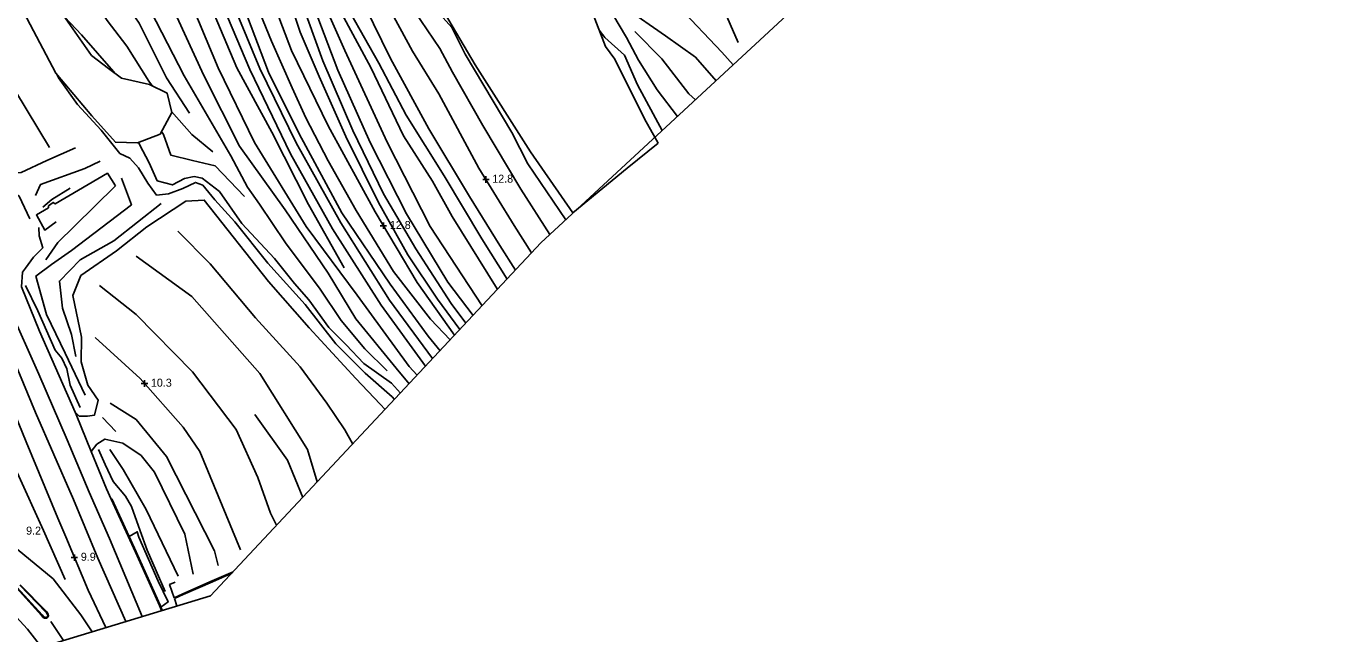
# Model space of a CAD drawing. Extents: x 2316231 to 2323598, y 363169 to 371906.
# Drawn here: x 2321107 to 2321928, y 365823 to 366202 of the extents above; entities that cross this region are included whole.
import ezdxf

# ---------------------------------------------------------------- set-up
doc = ezdxf.new("R2010")
doc.units = 0
for name, color, linetype in [('RD_DTM_BkLn1', 7, 'Continuous'), ('RD_DTM_Holes', 7, 'Continuous'), ('RD_DTM_TinHull', 7, 'Continuous'), ('RD_DTM_Void', 7, 'Continuous'), ('RD_EX_Road', 7, 'Continuous')]:
    doc.layers.add(name, color=color, linetype=linetype)

msp = doc.modelspace()

# ---------------------------------------------------------------- linework, layer by layer
at = {"layer": 'RD_DTM_BkLn1'}
for p, q in [((2321322.227, 366176.768), (2321286.129, 366244.099)), ((2321289.965, 366171.094), (2321277.994, 366198.719)), ((2321504.083, 366182.051), (2321487.214, 366199.217)), ((2321273.167, 366164.035), (2321260.269, 366193.113)), ((2321525.098, 366183.196), (2321537.836, 366168.43)), ((2321541.433, 366186.303), (2321548.52, 366178.333)), ((2321161.522, 366174.213), (2321162.22, 366173.211)), ((2321194.551, 366170.281), (2321208.955, 366148.228)), ((2321183.535, 366168.208), (2321185.773, 366165.108)), ((2321135.268, 366009.871), (2321137.957, 365996.082)), ((2321154.562, 365958.083), (2321162.89, 365949.247)), ((2321158.973, 365882.361), (2321179.414, 365833.696)), ((2321107.857, 365825.845), (2321116.44, 365814.555)), ((2321122.287, 365830.606), (2321130.227, 365818.746))]:
    msp.add_line(p, q, dxfattribs=at)
for points in [[(2321348.15, 366186.893), (2321331.232, 366218.438), (2321308.543, 366258.039), (2321292.715, 366289.297), (2321276.233, 366327.234), (2321257.319, 366369.632), (2321242.916, 366404.393), (2321227.689, 366445.074), (2321218.8, 366481.104), (2321211.429, 366515.501), (2321205.646, 366550.168), (2321200.699, 366594.349), (2321199.591, 366605.689)], [(2321301.702, 366175.097), (2321280.565, 366230.673), (2321263.475, 366276.886), (2321246.42, 366324.965), (2321229.201, 366379.671), (2321213.13, 366435.047), (2321200.953, 366481.482), (2321193.69, 366533.508), (2321189.529, 366581.697), (2321189.106, 366587.086)], [(2321292.167, 366180.958), (2321272.992, 366233.91), (2321255.426, 366283.859), (2321234.365, 366343.224), (2321216.164, 366402.709), (2321203.601, 366449.019), (2321195.314, 366487.774), (2321188.211, 366534.023), (2321184.436, 366578.801)], [(2321277.994, 366198.719), (2321258.305, 366258.009), (2321242.246, 366306.595), (2321223.445, 366361.989), (2321203.844, 366426.687), (2321190.102, 366483.073), (2321182.297, 366539.349), (2321179.687, 366570.375)], [(2321272.7, 366187.357), (2321259.187, 366223.155), (2321241.08, 366276.024), (2321219.601, 366347.455), (2321202.66, 366410.513), (2321186.289, 366461.213), (2321172.327, 366507.777), (2321166.852, 366547.603)], [(2321260.269, 366193.113), (2321240.792, 366240.711), (2321224.219, 366294.328), (2321207.131, 366346.117), (2321191.769, 366401.079), (2321171.604, 366468.511), (2321156.376, 366512.529), (2321153.71, 366524.287)], [(2321252.801, 366176.011), (2321231.979, 366226.491), (2321212.413, 366277.422), (2321195.559, 366329.186), (2321179.21, 366383.175), (2321162.803, 366442.321), (2321144.808, 366504.734), (2321144.106, 366507.248)], [(2321258.386, 366173.779), (2321242.805, 366214.365), (2321221.841, 366267.452), (2321204.934, 366313.185), (2321195.458, 366348.589), (2321191.131, 366367.553), (2321174.763, 366418.778), (2321160.755, 366467.057), (2321147.297, 366512.909)], [(2321327.165, 366179.472), (2321300.339, 366227.015), (2321278.298, 366267.649), (2321261.143, 366307.819), (2321239.141, 366360.878), (2321224.082, 366400.555), (2321212.067, 366448.483), (2321203.9, 366496.151)], [(2321238.425, 366176.556), (2321222.092, 366215.463), (2321205.055, 366259.307), (2321191.459, 366296.15), (2321183.264, 366326.085), (2321173.84, 366353.695), (2321159.577, 366397.181), (2321142.653, 366442.133), (2321123.393, 366483.161)], [(2321246.543, 366175.521), (2321216.416, 366246.921), (2321192.369, 366316.631), (2321175.26, 366368.689), (2321160.219, 366410.815), (2321138.931, 366462.563), (2321127.39, 366487.452)], [(2321226.83, 366176.404), (2321207.135, 366223.931), (2321188.206, 366277.599), (2321173.929, 366325.811), (2321158.597, 366363.074), (2321147.977, 366412.054), (2321131.316, 366452.804), (2321118.411, 366477.812)], [(2321217.85, 366171.777), (2321195.092, 366221.773), (2321177.651, 366264.476), (2321159.843, 366311.615), (2321145.632, 366336.983), (2321130.053, 366374.015), (2321112.686, 366422.481), (2321099.314, 366457.31)], [(2321205.698, 366171.431), (2321181.155, 366219.069), (2321161.671, 366246.316), (2321145.676, 366287.224), (2321131.683, 366315.53), (2321109.87, 366367.188), (2321090.922, 366404.593), (2321078.335, 366434.787)], [(2321511.284, 366313.643), (2321496.519, 366319.473), (2321484.027, 366320.013), (2321478.066, 366308.212), (2321479.658, 366290.223), (2321482.685, 366260.265), (2321481.649, 366243.589), (2321476.829, 366234.895), (2321468.495, 366229.189), (2321481.143, 366213.982), (2321506.351, 366196.403), (2321525.098, 366183.196)], [(2321306.074, 366187.392), (2321285.761, 366232.924), (2321262.685, 366291.02)], [(2321541.433, 366186.303), (2321514.561, 366214.605), (2321500.215, 366233.93), (2321495.065, 366255.432), (2321501.651, 366264.779), (2321512.378, 366258.732), (2321535.225, 366230.284), (2321551.695, 366192.277)], [(2321381.088, 366185.114), (2321372.744, 366201.657), (2321365.438, 366209.827), (2321362.911, 366215.561), (2321353.959, 366228.701), (2321353.362, 366236.235)], [(2321194.551, 366170.281), (2321177.542, 366204.311), (2321161.58, 366227.941)], [(2321455.195, 366229.198), (2321459.015, 366226.442), (2321462.737, 366221.353), (2321473.333, 366209.87), (2321481.88, 366195.503)], [(2321183.535, 366168.208), (2321169.755, 366189.956), (2321157.441, 366206.094), (2321146.286, 366222.901)], [(2321161.522, 366174.213), (2321141.489, 366197.161), (2321130.996, 366208.151)], [(2321121.498, 366126.801), (2321100.307, 366161.879), (2321090.1, 366195.438)], [(2321480.738, 366184.491), (2321468.334, 366195.356), (2321464.878, 366200.017)], [(2321481.88, 366195.503), (2321489.421, 366181.323), (2321500.985, 366162.838), (2321513.758, 366146.112)], [(2321272.7, 366187.357), (2321295.585, 366140.192), (2321324.959, 366086.53), (2321351.072, 366042.351), (2321374.541, 366009.457)], [(2321306.074, 366187.392), (2321332.414, 366130.151), (2321359.258, 366077.265), (2321391.724, 366027.81)], [(2321348.15, 366186.893), (2321364.743, 366160.239), (2321389.693, 366113.829), (2321411.738, 366078.055), (2321422.627, 366060.816)], [(2321292.167, 366180.958), (2321310.912, 366137.272), (2321330.156, 366097.692), (2321350.269, 366063.337), (2321372.395, 366029.323), (2321381.548, 366016.941)], [(2321327.165, 366179.472), (2321344.311, 366147.021), (2321368.067, 366109.11), (2321391.568, 366069.738), (2321407.336, 366044.484)], [(2321381.088, 366185.114), (2321410.249, 366136.134), (2321420.299, 366116.534), (2321444.024, 366081.475)], [(2321480.738, 366184.491), (2321488.743, 366165.791), (2321504.223, 366137.274)], [(2321504.083, 366182.051), (2321520.948, 366160.227), (2321525.075, 366156.602)], [(2321033.694, 366176.556), (2321049.251, 366136.951), (2321066.065, 366097.733), (2321080.078, 366064.138), (2321096.325, 366026.829), (2321114.881, 365985.178), (2321132.594, 365944.069), (2321146.359, 365911.495), (2321158.973, 365882.361)], [(2321217.367, 366103.276), (2321212.625, 366104.93), (2321204.731, 366101.187), (2321195.743, 366097.753), (2321188.43, 366096.97), (2321182.981, 366104.494), (2321177.014, 366114.093), (2321171.615, 366119.963), (2321165.471, 366122.934), (2321153.871, 366137.579), (2321139.085, 366153.645), (2321127.048, 366170.221), (2321126.144, 366172.319)], [(2321205.698, 366171.431), (2321221.677, 366143.993), (2321234.717, 366121.531), (2321245.215, 366101.866), (2321252.706, 366091.256), (2321268.811, 366067.267), (2321290.645, 366038.255), (2321303.614, 366018.737), (2321318.543, 366000.908), (2321332.317, 365987.135)], [(2321217.85, 366171.777), (2321240.157, 366127.55), (2321268.747, 366087.795), (2321295.543, 366048.263), (2321312.928, 366019.78), (2321338.116, 365988.765), (2321346.192, 365979.179)], [(2321226.83, 366176.404), (2321249.451, 366129.904), (2321281.758, 366077.317), (2321313.737, 366034.483), (2321346.059, 365989.836), (2321351.126, 365984.448)], [(2321238.425, 366176.556), (2321260.333, 366136.375), (2321283.311, 366091.077), (2321305.57, 366051.601)], [(2321246.543, 366175.521), (2321272.005, 366122.782), (2321298.214, 366075.883), (2321328.678, 366028.152), (2321356.365, 365990.044)], [(2321252.801, 366176.011), (2321275.554, 366129.71), (2321303.496, 366079.623), (2321333.953, 366031.325), (2321360.832, 365994.815)], [(2321258.386, 366173.779), (2321277.513, 366135.24), (2321304.118, 366085.985), (2321334.325, 366041.27), (2321358.076, 366008.761), (2321365.494, 365999.794)], [(2321289.965, 366171.094), (2321306.541, 366133.592), (2321327.089, 366092.436), (2321345.414, 366059.734), (2321363.86, 366032.005), (2321377.815, 366012.954)], [(2321301.702, 366175.097), (2321321.834, 366129.857), (2321344.395, 366085.19), (2321370.302, 366042.62), (2321386.041, 366021.739)], [(2321322.227, 366176.768), (2321342.555, 366134.043), (2321360.673, 366105.633), (2321372.938, 366083.571), (2321401.166, 366038.479), (2321401.4, 366038.144)], [(2321016.422, 366163.653), (2321030.631, 366126.842), (2321048.807, 366082.123), (2321067.3, 366038.239), (2321086.527, 365992.491), (2321107.017, 365942.839), (2321126.727, 365895.111), (2321131.653, 365883.468)], [(2321028.335, 366166.59), (2321046.266, 366121.165), (2321067.619, 366067.708), (2321091.625, 366011.903), (2321112.764, 365961.191), (2321135.654, 365908.779)], [(2321273.167, 366164.035), (2321281.561, 366145.247), (2321295.491, 366118.343), (2321313.082, 366087.422), (2321336.386, 366049.281), (2321359.556, 366019.425), (2321371.747, 366006.473)], [(2321107.857, 365825.845), (2321089.033, 365845.956), (2321064.914, 365868.827), (2321040.152, 365890.43), (2321013.859, 365911.449), (2320983.706, 365933.792), (2320958.395, 365951.148), (2320936.89, 365964.698), (2320914.976, 365977.721), (2320890.131, 365990.721), (2320868.682, 366001.198), (2320834.466, 366016.123), (2320800.88, 366029.386), (2320770.06, 366041.822), (2320731.461, 366056.849), (2320690.819, 366072.905), (2320650.247, 366088.926), (2320609.558, 366105.101), (2320574.835, 366119.134), (2320536.92, 366134.034), (2320494.89, 366150.627)], [(2321197.687, 366149.254), (2321210.444, 366134.867), (2321223.532, 366123.927)], [(2321216.793, 366107.549), (2321211.842, 366108.544), (2321205.741, 366107.355), (2321198.246, 366103.324), (2321188.754, 366105.994), (2321183.859, 366117.164), (2321177.738, 366128.632), (2321177.187, 366130.003)], [(2321191.455, 366136.714), (2321192.705, 366134.887), (2321197.237, 366121.973), (2321210.773, 366118.602), (2321225.078, 366115.175), (2321243.407, 366096.134)], [(2321153.217, 366118.241), (2321143.492, 366113.552), (2321115.787, 366103.697), (2321112.795, 366096.809)], [(2321109.125, 366082.059), (2321102.556, 366096.416), (2321095.113, 366101.366), (2321086.105, 366105.886)], [(2321143.851, 365972.008), (2321131.365, 365998.173), (2321119.67, 366022.32), (2321112.985, 366046.416), (2321122.648, 366053.73), (2321135.305, 366062.365), (2321172.673, 366090.996), (2321166.557, 366107.617)], [(2321216.793, 366107.549), (2321227.787, 366099.211), (2321241.601, 366079.174), (2321262.106, 366057.388), (2321274.534, 366041.788), (2321283.411, 366031.491), (2321295.924, 366014.188), (2321306.863, 366003.393), (2321317.805, 365991.841), (2321335.024, 365979.526), (2321340.644, 365973.252)], [(2321162.784, 366102.736), (2321137.149, 366077.634), (2321126.729, 366067.364), (2321119.149, 366056.515)], [(2321217.367, 366103.276), (2321224.803, 366094.036), (2321237.219, 366080.28), (2321257.933, 366054.426), (2321281.295, 366028.61), (2321300.288, 366004.006), (2321318.662, 365985.709), (2321335.543, 365970.928), (2321337.012, 365969.373)], [(2321191.318, 366091.663), (2321161.733, 366068.324), (2321140.705, 366056.59), (2321127.658, 366043.244), (2321129.564, 366026.392), (2321135.268, 366009.871)], [(2321201.729, 366074.457), (2321221.897, 366054.07), (2321250.148, 366020.393), (2321278.059, 365989.676), (2321294.748, 365967.027), (2321305.885, 365950.285), (2321310.88, 365941.463)], [(2321175.606, 366058.769), (2321210.392, 366033.591), (2321252.8, 365985.522), (2321282.723, 365937.975), (2321288.702, 365917.776)], [(2321152.667, 366040.571), (2321175.687, 366022.428), (2321210.719, 365986.611), (2321238.172, 365950.487), (2321251.532, 365920.458), (2321259.494, 365898.355), (2321263.365, 365890.714)], [(2321150.064, 366007.939), (2321178.109, 365982.395), (2321204.889, 365952.023)], [(2321159.377, 365967.076), (2321175.557, 365956.712), (2321194.592, 365933.585), (2321224.658, 365874.726), (2321226.777, 365865.494)], [(2321086.59, 365961.421), (2321101.344, 365923.753), (2321117.827, 365887.362), (2321131.321, 365856.776)], [(2321249.824, 365959.974), (2321270.234, 365931.476), (2321279.677, 365908.136)], [(2321204.889, 365952.023), (2321215.396, 365936.907), (2321240.81, 365875.447)], [(2321201.902, 365858.913), (2321181.891, 365900.535), (2321167.583, 365925.589), (2321159.17, 365937.995)], [(2321187.095, 365923.953), (2321206.115, 365885.119), (2321211.276, 365860.073)], [(2321135.418, 365909.318), (2321151.695, 365870.078), (2321169.155, 365830.578)], [(2321069.926, 365902.304), (2321097.808, 365878.807), (2321123.822, 365857.189)], [(2321131.653, 365883.468), (2321145.61, 365850.241), (2321156.736, 365826.803)], [(2321123.793, 365857.213), (2321141.164, 365834.732), (2321148.071, 365824.169)]]:
    msp.add_lwpolyline(points, dxfattribs=at)
at = {"layer": 'RD_DTM_Holes'}
for points in [[(2321501.645, 366129.374), (2321482.332, 366113.897), (2321448.482, 366085.954), (2321421.94, 366124.088), (2321387.469, 366178.393), (2321351.085, 366240.096), (2321315.164, 366306.702), (2321297.668, 366351.552), (2321303.671, 366367.891), (2321314.235, 366378.949), (2321333.048, 366393.462), (2321342.926, 366384.365), (2321363.992, 366353.117), (2321389.36, 366302.578), (2321408.27, 366278.473), (2321426.963, 366254.988), (2321441.718, 366233.98), (2321461.14, 366209.709), (2321468.798, 366189.851), (2321474.608, 366181.873), (2321493.077, 366144.596), (2321501.645, 366129.374)], [(2321158.426, 366176.083), (2321166.41, 366170.04), (2321183.862, 366166.03), (2321195.081, 366160.62), (2321197.85, 366148.543), (2321190.533, 366135.008), (2321176.38, 366129.7), (2321162.629, 366130.048), (2321147.956, 366146.598), (2321125.36, 366173.244), (2321103.426, 366214.922), (2321089.457, 366246.833), (2321098.094, 366247.287), (2321119.996, 366223.886), (2321147.771, 366184.157), (2321158.426, 366176.083)]]:
    msp.add_lwpolyline(points, dxfattribs=at)
at = {"layer": 'RD_DTM_TinHull'}
msp.add_lwpolyline([(2322749.057, 368805.183), (2322437.788, 368637.943), (2322185.484, 368501.144), (2321988.712, 368397.613), (2321906.574, 368261.806), (2321814.258, 368125.896), (2321753.197, 367969.571), (2321734.081, 367792.897), (2321812.341, 367285.803), (2321826.603, 366879.552), (2321787.983, 366568.052), (2321665.825, 366287.064), (2321428.475, 366067.062), (2321222.139, 365846.682), (2320971.939, 365770.635), (2320807.161, 365571.8), (2320809.363, 365353.877), (2320991.706, 364942.038)], dxfattribs=at)
at = {"layer": 'RD_DTM_Void'}
for p, q in [((2321392.07, 366106.726), (2321396.07, 366106.726)), ((2321394.07, 366104.726), (2321394.07, 366108.726)), ((2321330.104, 366075.826), (2321330.104, 366079.826)), ((2321328.104, 366077.826), (2321332.104, 366077.826)), ((2321180.852, 365977.285), (2321180.852, 365981.285)), ((2321178.852, 365979.285), (2321182.852, 365979.285)), ((2321135.08, 365870.549), (2321139.08, 365870.549)), ((2321137.08, 365868.549), (2321137.08, 365872.549))]:
    msp.add_line(p, q, dxfattribs=at)
at = {"layer": 'RD_EX_Road'}
for p, q in [((2321160.489, 365907.172), (2321171.246, 365883.626)), ((2321201.128, 365840.296), (2321199.657, 365844.914)), ((2321191.12, 365839.503), (2321191.988, 365837.518))]:
    msp.add_line(p, q, dxfattribs=at)
for points in [[(2321334.587, 366182.405), (2321318.55, 366215.036), (2321293.936, 366256.33), (2321282.098, 366280.737), (2321267.359, 366314.286), (2321252.429, 366348.934), (2321240.372, 366380.505), (2321224.758, 366414.072), (2321213.387, 366452.079), (2321206.024, 366489.439), (2321199.566, 366531.076), (2321193.372, 366577.295), (2321191.878, 366592.004)], [(2321268.997, 366369.705), (2321290.064, 366328.154), (2321308.075, 366288.597), (2321325.915, 366254.676), (2321345.519, 366217.769), (2321365.212, 366188.525)], [(2321365.212, 366188.525), (2321373.135, 366173.749), (2321392.115, 366140.495), (2321415.825, 366100.789), (2321434.092, 366072.268)], [(2321334.587, 366182.405), (2321358.349, 366138.338), (2321383.882, 366096.021), (2321402.707, 366065.475), (2321412.555, 366050.059)], [(2321093.453, 366117.294), (2321094.901, 366112.1), (2321098.311, 366110.734), (2321103.717, 366111.151), (2321119.823, 366118.633), (2321137.696, 366126.589)], [(2321125.74, 366080.223), (2321118.515, 366075.113), (2321113.327, 366084.631), (2321120.851, 366089.111), (2321120.783, 366090.258), (2321123.87, 366092.442), (2321125.052, 366091.47), (2321139.694, 366100.057), (2321157.635, 366110.659), (2321162.784, 366102.736)], [(2321134.51, 366101.327), (2321122.959, 366094.226), (2321117.25, 366089.345)], [(2321137.469, 365961.312), (2321140.093, 365958.902), (2321145.269, 365958.909), (2321149.543, 365959.482), (2321151.931, 365968.882), (2321145.535, 365978.25), (2321141.368, 365992.908), (2321141.39, 366008.165), (2321136.088, 366034.171), (2321141.017, 366046.684), (2321163.319, 366062.077), (2321182.356, 366077.216), (2321206.698, 366093.198), (2321218.169, 366093.848), (2321258.392, 366043.041), (2321283.594, 366014.07), (2321312.804, 365982.403), (2321328.11, 365966.377), (2321331.165, 365963.129)], [(2321114.8, 366076.683), (2321115.032, 366071.563), (2321117.278, 366064.055), (2321111.426, 366058.16), (2321106.46, 366051.237), (2321104.727, 366048.753), (2321103.908, 366039.636)], [(2321103.908, 366039.636), (2321115.32, 366011.94), (2321137.469, 365961.312)], [(2321106.552, 366040.588), (2321114.274, 366024.775), (2321125.099, 366000.036), (2321129.269, 365995.163), (2321132.388, 365988.388), (2321134.423, 365978.152), (2321140.693, 365964.39)], [(2321137.469, 365961.312), (2321138.073, 365959.932), (2321147.548, 365936.743)], [(2321147.548, 365936.743), (2321150.995, 365941.3), (2321156.117, 365944.557), (2321167.289, 365942.043), (2321178.692, 365934.327), (2321187.095, 365923.953)], [(2321147.548, 365936.743), (2321157.02, 365913.56), (2321160.034, 365906.965)], [(2321152.054, 365938.096), (2321156.369, 365928.648), (2321161.189, 365918.046), (2321168.897, 365908.804), (2321172.766, 365902.493), (2321178.097, 365887.347), (2321182.435, 365875.086), (2321193.661, 365849.29)], [(2321160.034, 365906.965), (2321175.129, 365873.924), (2321190.125, 365840.53), (2321191.506, 365837.371)], [(2321171.246, 365883.626), (2321176.34, 365886.707), (2321177.397, 365883.35), (2321189.357, 365855.796), (2321195.589, 365842.79), (2321191.12, 365839.503)], [(2321171.246, 365883.626), (2321175.585, 365874.13), (2321190.582, 365840.733), (2321191.12, 365839.503)], [(2321199.448, 365845.368), (2321204.883, 365847.867), (2321223.009, 365855.94), (2321236.191, 365861.69)], [(2321199.657, 365844.914), (2321205.089, 365847.411), (2321223.211, 365855.482), (2321235.328, 365860.768)], [(2321116.496, 365834.389), (2321100.862, 365851.6)], [(2321116.865, 365834.726), (2321101.228, 365851.941)], [(2321102.918, 365853.228), (2321119.214, 365836.462), (2321119.643, 365836.011), (2321120.225, 365835.067), (2321120.374, 365834.182), (2321120.132, 365833.529), (2321119.848, 365833.273), (2321119.455, 365833.142), (2321118.987, 365833.167), (2321118.534, 365833.22), (2321117.952, 365833.543), (2321116.865, 365834.726)], [(2321103.274, 365853.579), (2321119.575, 365836.809), (2321120.041, 365836.318), (2321120.702, 365835.246), (2321120.889, 365834.133), (2321120.559, 365833.239), (2321120.105, 365832.831), (2321119.523, 365832.638), (2321118.944, 365832.668), (2321118.378, 365832.735), (2321117.639, 365833.145), (2321116.496, 365834.389)], [(2321199.448, 365845.368), (2321196.493, 365853.698), (2321199.949, 365855.121)]]:
    msp.add_lwpolyline(points, dxfattribs=at)

# ---------------------------------------------------------------- texts
at = {"layer": 'RD_DTM_Void'}
for s, p in [('12.8', (2321398.07, 366104.726)), ('12.8', (2321334.104, 366075.826)), ('10.3', (2321184.852, 365977.285)), ('9.2', (2321106.895, 365884.862)), ('9.9', (2321141.08, 365868.549))]:
    msp.add_text(s, height=5, dxfattribs=at).set_placement(p)

doc.saveas('drawing.dxf')
